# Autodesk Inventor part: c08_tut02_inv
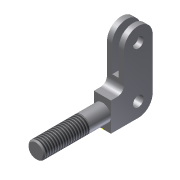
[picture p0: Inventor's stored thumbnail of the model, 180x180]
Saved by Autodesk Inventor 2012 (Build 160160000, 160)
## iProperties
Created: 2010-03
Part Number: c08_tut02_inv
Document SubType Name: Modeling
Designer: CADSoft
Density: 1 g/cm^3
Material: Default
Author: CADSoft
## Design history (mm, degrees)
sketch "Sketch1"
  geometry: 1 further point
sketch "Sketch2"
  geometry: L1 (0, 22)-(0, 0); L2 (0, 0)-(21, 0); L3 (32, 11)-(32, 50); L4 (10, 50)-(10, 27); L5 (5, 22)-(0, 22); C1 r 4 at (21, 50); C2 r 4 at (21, 11); A1 r 11 centre (21, 50) between (32, 50) and (10, 50); A2 r 11 centre (21, 11) between (21, 0) and (32, 11); A3 r 5 centre (5, 27) between (5, 22) and (10, 27); 1 further point
  constraints: 10 end point, 6 point on circle, 6 tangent, 5 centre point, 3 parallel, 2 coincident, 2 point on line, 1 equal radius, 1 perpendicular, 1 vertical
  dimensions: "d0" = 22 distance of L1.start L1.end; "d1" = 32 distance of L1.end point (32, 0); "d2" = 11 radius of A2; "d3" = 50 distance from line of A1.centre L2; "d4" = 11 radius of A1; "d5" = 5 radius of A3; "d6" = 8 diameter of C1
extrude "Extrusion1" new body sketch "Sketch2" stored distance "d7" = 13; taper "d8" = 0 deg
sketch "Sketch4"
  geometry: L1 (9, -19)-(4, -19); L2 (4, -19)-(4, -50); L3 (4, -50)-(9, -50); L4 (9, -50)-(9, -19); L5 (0, -50)-(0, -39) reference; 1 further point
  constraints: 8 end point, 2 parallel, 1 horizontal, 1 perpendicular, 1 point on line
  dimensions: "d12" = 5 distance of L2.end L3.end; "d15" = 30 distance from line of L1 point (6.5, 11)
extrude "Extrusion3" cut sketch "Sketch4" stored distance "d16" = 5; taper "d17" = 0 deg
sketch "Sketch5"
  geometry: C1 r 6.5 at (6.5, -11); 1 further point
  constraints: 1 centre point
  dimensions: "d18" = 13 diameter of C1
extrude "Extrusion4" join sketch "Sketch5" distance "d19" = 51; taper "d20" = 0 deg
chamfer "Chamfer1" distance "d21" = 1; stored, may be unused: second distance "d22" = 2, angle "d23" = 45 deg
thread "Thread1" dims "d24" = 34, "d25" = 0
body "Solid1"
